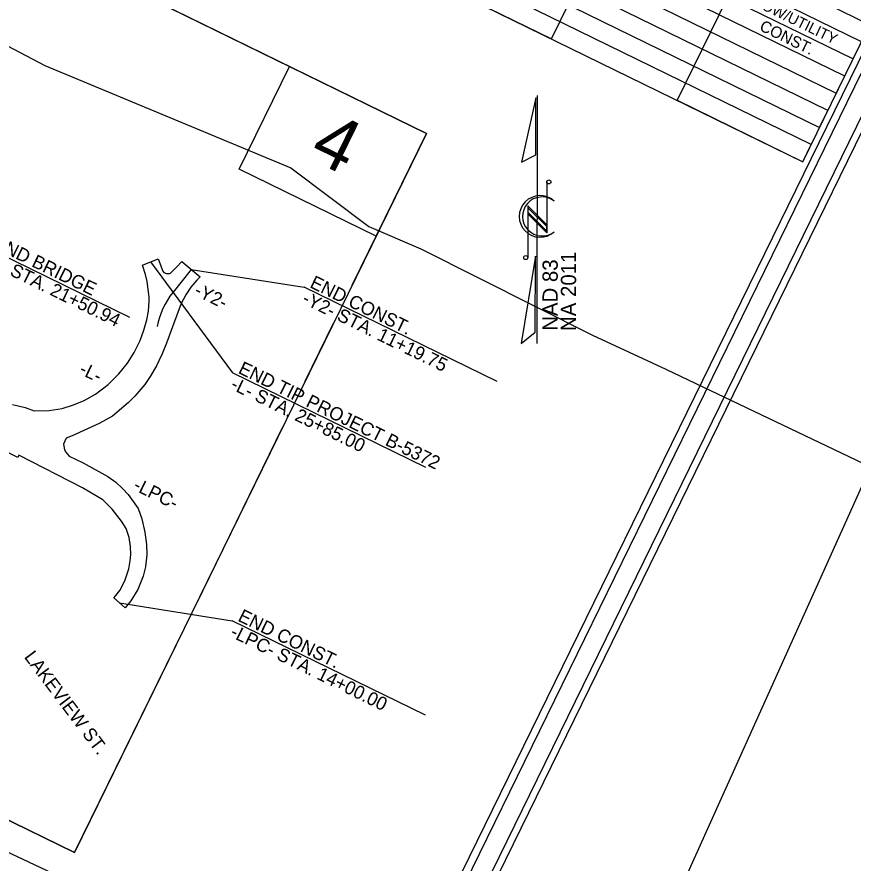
# Model space of a CAD drawing. Extents: x 1517888 to 1526099, y 633375 to 640181.
# Drawn here: x 1520641 to 1521738, y 637474 to 638583 of the extents above; entities that cross this region are included whole.
import ezdxf

# ---------------------------------------------------------------- set-up
doc = ezdxf.new("R2010")
doc.units = 0
for name, color, linetype in [('Prop Horizontal Alignment', 7, 'Continuous'), ('Prop Shade Light', 7, 'Continuous'), ('Scratch_Level_0', 7, 'Continuous'), ('Sheet Clip Boundary CELL', 7, 'Continuous'), ('Sheet Data Field CELL', 7, 'Continuous'), ('Sheet North Arrow CELL', 7, 'Continuous'), ('Sheet Plot Border Inside CELL', 7, 'Continuous'), ('Sheet Plot Border Outside CELL', 7, 'Continuous'), ('Sheet Title CELL', 7, 'Continuous')]:
    doc.layers.add(name, color=color, linetype=linetype)

msp = doc.modelspace()

# ---------------------------------------------------------------- linework, layer by layer
at = {"layer": 'Prop Horizontal Alignment'}
msp.add_line((1520869.8, 638252.2), (1520844.2, 638220.2), dxfattribs=at)
msp.add_arc((1520926.1, 638157.6), 103, 141.3588, 169.0742, dxfattribs=at)
at = {"layer": 'Prop Shade Light'}
msp.add_lwpolyline([(1520635.2, 638074.9), (1520651.8, 638071.1), (1520663.6, 638066.6), (1520683.6, 638066.9), (1520700.7, 638069.9), (1520715.5, 638074.6), (1520729.4, 638080.2), (1520744.2, 638088.5), (1520760.9, 638101.2), (1520775, 638115.3), (1520786.1, 638129.1), (1520794.9, 638143.3), (1520802.6, 638159), (1520807.6, 638172.5), (1520811.4, 638185.8), (1520813.5, 638197.2), (1520814.8, 638211), (1520814.5, 638215.7), (1520813.8, 638222.9), (1520811.8, 638236.1), (1520809.6, 638245.3), (1520806, 638257.7), (1520826.4, 638266.1), (1520832.6, 638249.9), (1520834, 638248.1), (1520837.2, 638246.7), (1520839.4, 638246.6), (1520841.4, 638246.8), (1520842.4, 638247.1), (1520845, 638249.7), (1520850.4, 638255.2), (1520857.3, 638262.6), (1520881.4, 638242.5), (1520876.9, 638237.9), (1520869.4, 638228.9), (1520862.6, 638218.6), (1520856.5, 638207.6), (1520845, 638176.9), (1520837.5, 638155.6), (1520831.5, 638141.5), (1520827.2, 638132.1), (1520824, 638125.6), (1520816.1, 638111.6), (1520808.8, 638101.2), (1520795.9, 638085.9), (1520787.6, 638077.6), (1520766.6, 638059.7), (1520748.9, 638050.1), (1520713.5, 638033.8), (1520705.6, 638030.8), (1520702.2, 638023.1), (1520703.5, 638015.6), (1520705.3, 638012.6), (1520709.5, 638007.2), (1520727.9, 637998.3), (1520760.4, 637980.6), (1520770.8, 637973), (1520780, 637964.5), (1520787.1, 637957), (1520800.1, 637938.4), (1520805, 637924.8), (1520808.8, 637907.4), (1520811, 637891.2), (1520811.4, 637877.7), (1520809.9, 637862.1), (1520806.7, 637849.6), (1520799.7, 637832.4), (1520790.5, 637817.3), (1520783, 637808.2), (1520768.3, 637821.3), (1520771, 637824.3), (1520776.1, 637831.2), (1520779.5, 637837.7), (1520783, 637844.8), (1520787.9, 637859.6), (1520789.5, 637870.1), (1520790.5, 637878.3), (1520789.9, 637888.5), (1520788.3, 637900.5), (1520785.9, 637908.2), (1520784.5, 637912.4), (1520778.1, 637922.1), (1520765.9, 637937.7), (1520753.9, 637950.1), (1520727, 637965.7), (1520643.5, 638008.3), (1520642.5, 638005.6), (1520557.7, 638047.2)], dxfattribs=at)
at = {"layer": 'Scratch_Level_0'}
msp.add_lwpolyline([(1519830.7, 639089.6), (1521178.1, 638430.5), (1520716.8, 637487.3), (1519369.3, 638146.3)], close=True, dxfattribs=at)
at = {"layer": 'Sheet Clip Boundary CELL'}
msp.add_lwpolyline([(1519997.2, 638878.2), (1520677.9, 638519.7), (1521000.4, 638385.3), (1521102.7, 638308.6), (1521171, 638278.9), (1521396, 638166), (1521492.2, 638121.5), (1521760.4, 637993.1), (1521455.7, 637316.3), (1521359.7, 637143.3), (1520290, 637647.3), (1519534.4, 638030.1)], close=True, dxfattribs=at)
at = {"layer": 'Sheet Data Field CELL'}
for p, q in [((1520601.2, 638281.4), (1520788.6, 638189.7)), ((1520816.2, 638261.9), (1520923.9, 638116.4)), ((1520869.8, 638252.2), (1521017.7, 638228.8)), ((1521271, 638104.9), (1521017.7, 638228.8)), ((1521177.3, 637992.4), (1520923.9, 638116.4)), ((1520775.6, 637814.8), (1520923.5, 637791.4)), ((1521176.9, 637667.5), (1520923.5, 637791.4))]:
    msp.add_line(p, q, dxfattribs=at)
at = {"layer": 'Sheet North Arrow CELL'}
for p, q in [((1521323.5, 638155.1), (1521323.9, 638480.1)), ((1521336, 638367), (1521335.9, 638300.3)), ((1521311.1, 638335.5), (1521311, 638267.7)), ((1521335.9, 638310.7), (1521311.1, 638335.5)), ((1521345.2, 638342.1), (1521345.5, 638341.8)), ((1521335.9, 638308.2), (1521311.1, 638333.1)), ((1521311.1, 638333.1), (1521311.1, 638327)), ((1521335.9, 638302.1), (1521311.1, 638327)), ((1521311.1, 638327), (1521335.9, 638302.1)), ((1521335.9, 638300.3), (1521311.1, 638325.1)), ((1521335.9, 638302.1), (1521335.9, 638308.2))]:
    msp.add_line(p, q, dxfattribs=at)
for points in [[(1521321.6, 638477.2), (1521303, 638392.8), (1521321.6, 638402.2)], [(1521321, 638269.6), (1521302.5, 638155.1), (1521320.9, 638169.6)]]:
    msp.add_lwpolyline(points, close=True, dxfattribs=at)
for centre in [(1521338.7, 638366.9), (1521308.4, 638267.6)]:
    msp.add_circle(centre, 2.65, dxfattribs=at)
for centre, radius, start, end in [((1521327.2, 638321.6), 27.3, 47.7724, 312.3265), ((1521329.8, 638321.6), 25.6, 53.0274, 308.5611)]:
    msp.add_arc(centre, radius, start, end, dxfattribs=at)
at = {"layer": 'Sheet Plot Border Inside CELL'}
msp.add_lwpolyline([(1517931.1, 638233.4), (1520925.2, 636769.1), (1521852.3, 638664.7), (1518858.2, 640129.1)], close=True, dxfattribs=at)
at = {"layer": 'Sheet Plot Border Outside CELL'}
msp.add_lwpolyline([(1521880.1, 638701.1), (1518854.6, 640180.8), (1517888, 638204.5), (1520913.6, 636724.8)], close=True, dxfattribs=at)
at = {"layer": 'Sheet Title CELL'}
for points in [[(1521803.5, 638662.9), (1521309.5, 638904.5), (1521177.7, 638635), (1521342.3, 638554.5), (1521441.2, 638756.6), (1521343.9, 638804.2), (1521376.8, 638871.6), (1521668.8, 638728.7), (1521635.8, 638661.4), (1521605.8, 638676.1), (1521507, 638474), (1521671.7, 638393.4), (1521803.5, 638662.9), (1521736.2, 638695.8), (1521703.2, 638628.4)], [(1521177.7, 638635), (1521671.7, 638393.4), (1521682.7, 638415.8), (1521188.6, 638657.5), (1521199.6, 638679.9), (1521693.7, 638438.3), (1521704.7, 638460.7), (1521210.6, 638702.4), (1521221.6, 638724.9), (1521715.7, 638483.2), (1521726.7, 638505.7), (1521232.6, 638747.3), (1521243.5, 638769.8), (1521737.6, 638528.1), (1521748.6, 638550.6), (1521254.5, 638792.2), (1521265.5, 638814.7), (1521759.6, 638573)], [(1521080.8, 638231.4), (1521178.2, 638430.5), (1520477.5, 638773.2)], [(1520913.8, 636802.6), (1521818.8, 638653.2)], [(1521071.7, 637148.4), (1521805.5, 638648.6)], [(1521112.2, 638295.7), (1520932.5, 638383.6), (1520998.4, 638518.4)], [(1519396, 638200.8), (1519369.3, 638146.3), (1520716.8, 637487.3)], [(1521019.3, 638105.6), (1521056.5, 638181.6)], [(1520876.5, 637813.7), (1520876.5, 637813.7), (1520989.9, 638045.6)], [(1520716.8, 637487.3), (1520716.8, 637487.3), (1520858.6, 637777.1)]]:
    msp.add_lwpolyline(points, dxfattribs=at)

# ---------------------------------------------------------------- texts
at = {"layer": 'Sheet Data Field CELL'}
for s, height, rotation, p in [('ROW/UTILITY', 14, 333.9377, (1521604.5, 638599.9)), ('CONST.', 15, 333.9377, (1521613.8, 638566.3)), ('4', 70, 333.9377, (1521022.2, 638398.5)), ('END BRIDGE', 17.5, 333.9377, (1520609, 638281.2)), ('-L- STA. 21+50.94', 17.5, 333.9377, (1520599, 638260.5)), ('END CONST.', 17.5, 333.9377, (1521024, 638229.1)), ('-Y2-', 17.5, 333.9377, (1520872.3, 638219.2)), ('-Y2- STA. 11+19.75', 17.5, 333.9377, (1521013.9, 638208.5)), ('-L-', 17.5, 333.9377, (1520721.7, 638115.8)), ('END TIP PROJECT B-5372', 17.5, 333.9377, (1520930.2, 638116.6)), ('-L- STA. 25+85.00', 17.5, 333.9377, (1520920.1, 638096)), ('-LPC-', 17.5, 333.9377, (1520792.5, 637963.7)), ('END CONST.', 17.5, 333.9377, (1520929.8, 637791.7)), ('-LPC- STA. 14+00.00', 17.5, 333.9377, (1520919.7, 637771.1)), ('LAKEVIEW ST.', 17.5, 307.0152, (1520649.9, 637743.7))]:
    msp.add_text(s, height=height, rotation=rotation, dxfattribs=at).set_placement(p)
at = {"layer": 'Sheet North Arrow CELL'}
for s, p in [('NA 2011', (1521374.4, 638171.4)), ('NAD 83', (1521350.3, 638171.6))]:
    msp.add_text(s, height=20, rotation=89.9324, dxfattribs=at).set_placement(p)

doc.saveas('drawing.dxf')
